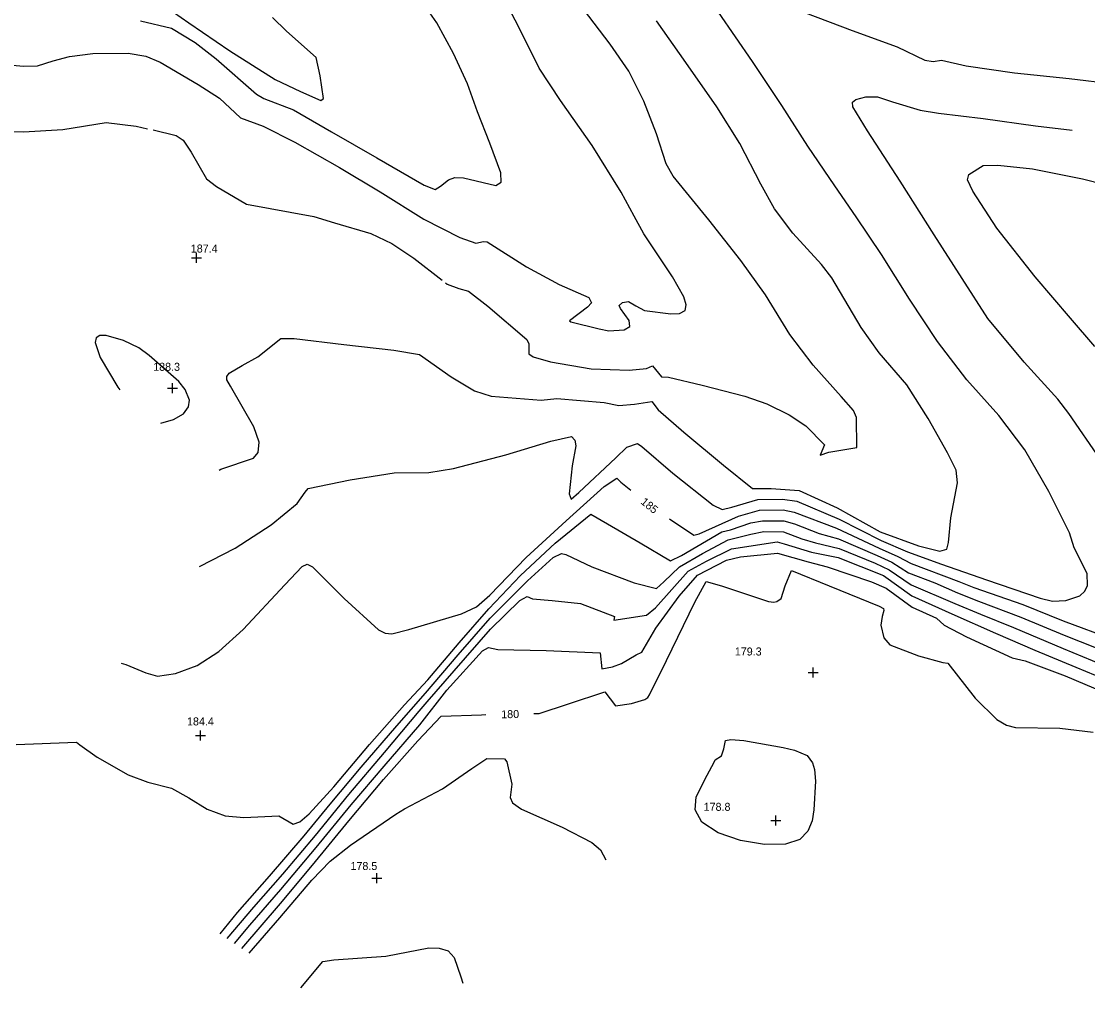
# Model space of a CAD drawing. Extents: x 1467615 to 2003689, y 770235 to 1108726.
# Drawn here: x 1995231.2 to 1995497.6, y 776742.8 to 776984.1 of the extents above; entities that cross this region are included whole.
import ezdxf

# ---------------------------------------------------------------- set-up
doc = ezdxf.new("R2010")
doc.units = 0
for name, color, linetype in [('RD_DTM_Major1', 7, 'Continuous'), ('RD_DTM_Major1_Lbl', 7, 'Continuous'), ('RD_DTM_Minor1', 7, 'Continuous'), ('RD_DTM_Spot_Elev', 7, 'Continuous')]:
    doc.layers.add(name, color=color, linetype=linetype)

msp = doc.modelspace()

# ---------------------------------------------------------------- linework, layer by layer
at = {"layer": 'RD_DTM_Major1'}
for points in [[(1995261.03, 776984.21), (1995268.76, 776982.39), (1995274.67, 776978.74), (1995279.91, 776974.68), (1995289.96, 776965.88), (1995291.8, 776964.78), (1995299.26, 776961.94), (1995308.7, 776956.45), (1995320.06, 776949.96), (1995331.84, 776943.17), (1995334.63, 776942.12), (1995335.96, 776942.91), (1995337.91, 776944.52), (1995339.51, 776945.04), (1995341.68, 776945.01), (1995349.73, 776943.07), (1995351.1, 776943.87), (1995351.03, 776946.28), (1995348.29, 776953.61), (1995345.17, 776961.45), (1995342.71, 776968.47), (1995339.23, 776976.07), (1995334.99, 776983.68), (1995329.2, 776992.08)], [(1995500.84, 776874.64), (1995492.92, 776886.19), (1995490.12, 776889.74), (1995481.78, 776898.96), (1995472.65, 776909.85), (1995466.23, 776919.89), (1995459.29, 776930.79), (1995450.75, 776944.13), (1995442.63, 776956.69), (1995438.94, 776962.71), (1995438.84, 776963.87), (1995439.7, 776964.51), (1995442.23, 776965.25), (1995445.13, 776965.19), (1995448.82, 776963.94), (1995455.8, 776961.9), (1995460.38, 776961.11), (1995471.53, 776959.8), (1995484.54, 776958.01), (1995493.76, 776956.9)], [(1995256.14, 776823.79), (1995257.37, 776823.52), (1995262.34, 776821.39), (1995265.28, 776820.62), (1995269.77, 776821.25), (1995275.17, 776823.28), (1995280.6, 776826.72), (1995286.69, 776832.21), (1995297.04, 776843.38), (1995301.4, 776848), (1995302.67, 776848.54), (1995303.96, 776847.91), (1995311.85, 776840.01), (1995320.45, 776832.16), (1995322.16, 776831.32), (1995323.75, 776831.19), (1995328.03, 776832.26), (1995341.19, 776836.15), (1995344.9, 776837.87), (1995348.28, 776840.77), (1995357.31, 776850.19), (1995367.34, 776859.4), (1995376.79, 776867.94), (1995380.01, 776870.02), (1995381.01, 776869), (1995383.45, 776867.01)], [(1995393.11, 776859.87), (1995399.25, 776855.78), (1995400.57, 776856.08), (1995410.42, 776860.56), (1995415.59, 776862.01), (1995421.53, 776862.08), (1995424.32, 776861.54), (1995434.84, 776857.56), (1995445.54, 776852.57), (1995450.21, 776850.49), (1995453.48, 776848.69), (1995465.42, 776844.19), (1995469.16, 776842.71), (1995481.38, 776838.45), (1995491.5, 776834.36), (1995504.07, 776829.72)], [(1995359.25, 776811.23), (1995360.57, 776811.25), (1995367.96, 776813.66), (1995377.02, 776816.68), (1995379.68, 776813.2), (1995383.64, 776813.76), (1995387, 776814.77), (1995387.7, 776815.26), (1995388.14, 776815.94), (1995392.36, 776824.49), (1995399.45, 776839.06), (1995402.27, 776844.25), (1995406.11, 776843.11), (1995417.85, 776839.22), (1995419.25, 776839.06), (1995419.95, 776839.18), (1995421.03, 776839.97), (1995422.06, 776843.1), (1995423.66, 776846.93), (1995433.01, 776843.13), (1995445.51, 776838.09), (1995446.63, 776837.49), (1995446.73, 776837.01), (1995446.26, 776835.48), (1995445.97, 776833.3), (1995446.7, 776830.18), (1995448.17, 776828.4), (1995455.35, 776825.65), (1995461.42, 776823.98), (1995462.69, 776823.81), (1995469.48, 776815.1), (1995474.93, 776809.75), (1995477.33, 776808.35), (1995479.55, 776807.77), (1995490.64, 776807.61), (1995498.98, 776806.58)], [(1995286.29, 776752.63), (1995296, 776763.85), (1995303.96, 776773.36), (1995313.03, 776784.48), (1995321.73, 776794.77), (1995330.27, 776804.41), (1995336.08, 776810.6), (1995346.18, 776810.96), (1995347.25, 776810.98)]]:
    msp.add_lwpolyline(points, dxfattribs=at)
at = {"layer": 'RD_DTM_Minor1'}
for points in [[(1995218, 776974.14), (1995231.79, 776972.88), (1995235.24, 776972.99), (1995239.16, 776974.21), (1995243.25, 776975.3), (1995249.13, 776976.03), (1995257.95, 776976.13), (1995262.3, 776975.37), (1995265.89, 776973.85), (1995275.45, 776968.3), (1995280.73, 776964.92), (1995286.02, 776959.93), (1995291.64, 776957.92), (1995299.54, 776953.87), (1995310.73, 776947.61), (1995320.91, 776941.53), (1995331.81, 776934.7), (1995340.8, 776930.11), (1995344.78, 776928.68), (1995346.69, 776929.07), (1995347.57, 776929.02), (1995357.42, 776922.75), (1995365.57, 776918.34), (1995372.96, 776915.13), (1995373.67, 776913.79), (1995372.64, 776912.68), (1995368.14, 776909.25), (1995368.54, 776909.05), (1995375.61, 776907.26), (1995378, 776906.8), (1995381.81, 776907.04), (1995383.27, 776907.86), (1995383.1, 776909.39), (1995380.88, 776912.35), (1995380.56, 776913.12), (1995381.43, 776913.87), (1995382.92, 776914.08), (1995384.76, 776913.06), (1995386.87, 776911.89), (1995393.51, 776911.04), (1995395.64, 776911.15), (1995397.04, 776911.84), (1995397.34, 776913.26), (1995396.72, 776915.29), (1995393.87, 776920.31), (1995386.77, 776931.03), (1995384.31, 776935.39), (1995381.09, 776941.44), (1995373.85, 776953.03), (1995365.92, 776964.31), (1995360.58, 776972.4), (1995355.34, 776982.93), (1995349.47, 776994.18)], [(1995337.18, 776918.8), (1995337.62, 776918.45), (1995340.56, 776917.4), (1995342.92, 776916.68), (1995347.75, 776912.95), (1995357.48, 776904.59), (1995357.99, 776903.54), (1995358.04, 776901.08), (1995359.08, 776900.28), (1995363.41, 776899.09), (1995373.61, 776897.34), (1995383.1, 776896.96), (1995387.39, 776897.42), (1995388.91, 776898.09), (1995391.14, 776895.33), (1995392.87, 776895.23), (1995401.33, 776893.22), (1995411.95, 776890.45), (1995417.49, 776888.61), (1995423.03, 776885.84), (1995427.18, 776883.07), (1995431.88, 776878.31), (1995430.79, 776875.76), (1995432.96, 776876.53), (1995439.95, 776877.68), (1995439.82, 776885.15), (1995439.11, 776886.91), (1995436, 776890.43), (1995429.04, 776898.2), (1995423.19, 776905.89), (1995417.11, 776915.82), (1995410.94, 776924.37), (1995402.98, 776934.5), (1995394.04, 776945.4), (1995392.28, 776948.51), (1995389.92, 776955.95), (1995386.76, 776964.15), (1995382.99, 776971.64), (1995378.35, 776978.36), (1995370.36, 776988.85)], [(1995267.35, 776987.72), (1995273.04, 776983.67), (1995283.31, 776976.69), (1995294.64, 776969.57), (1995300.95, 776966.58), (1995306.08, 776964.33), (1995306.68, 776964.79), (1995305.9, 776970.47), (1995304.87, 776975.03), (1995297.44, 776981.58), (1995294.01, 776985.01)], [(1995275.76, 776847.97), (1995284.67, 776852.55), (1995293.63, 776858.38), (1995300.18, 776863.68), (1995302.12, 776866.54), (1995302.9, 776867.47), (1995313.36, 776869.58), (1995324.36, 776871.33), (1995333.05, 776871.41), (1995339.23, 776872.45), (1995352.28, 776875.84), (1995363.53, 776879.29), (1995368.68, 776880.42), (1995369.52, 776879.49), (1995369.76, 776878.08), (1995368.81, 776873.11), (1995368.09, 776866.09), (1995368.59, 776864.77), (1995370.52, 776866.43), (1995379.73, 776875.1), (1995382.46, 776877.77), (1995385.15, 776878.67), (1995386.23, 776877.93), (1995393.97, 776871.25), (1995404.09, 776863.23), (1995406.27, 776862.2), (1995408.71, 776862.78), (1995415.2, 776864.69), (1995421.39, 776864.76), (1995424.94, 776864.25), (1995435.5, 776859.77), (1995446.05, 776854.46), (1995452.61, 776851.63), (1995461.08, 776848.58), (1995472.34, 776844.6), (1995485.72, 776840.03), (1995488.8, 776839.3), (1995492.11, 776839.46), (1995495.63, 776840.67), (1995496.9, 776841.77), (1995497.6, 776843.2), (1995497.49, 776846.22), (1995494.23, 776852.65), (1995493.05, 776856.33), (1995487.93, 776866.67), (1995481.95, 776877.12), (1995475.41, 776885.67), (1995467.4, 776894.56), (1995460.11, 776904.1), (1995453.09, 776914.74), (1995446.1, 776925.84), (1995439.8, 776935.24), (1995434.49, 776942.96), (1995427.72, 776952.93), (1995421.21, 776963.09), (1995413.91, 776974), (1995405.43, 776986.35)], [(1995427.16, 776986.17), (1995438.79, 776981.81), (1995450.02, 776977.73), (1995456.92, 776974.36), (1995459.02, 776974.05), (1995461.06, 776974.35), (1995467.25, 776972.98), (1995479.32, 776971.2), (1995492.96, 776969.77), (1995504.07, 776968.43)], [(1995280.62, 776871.98), (1995281.04, 776872.23), (1995289.21, 776875.04), (1995290.43, 776876.45), (1995290.68, 776878.97), (1995289.32, 776882.84), (1995283.46, 776892.98), (1995282.57, 776894.52), (1995282.56, 776895.37), (1995283.15, 776896.26), (1995286.37, 776898.15), (1995290.3, 776900.3), (1995296.04, 776904.92), (1995299.43, 776904.87), (1995311.8, 776903.41), (1995324.26, 776901.97), (1995330.66, 776900.88), (1995338.6, 776895.32), (1995344.43, 776891.84), (1995348.63, 776890.49), (1995361.06, 776889.48), (1995364.99, 776889.89), (1995376.87, 776888.87), (1995380.52, 776888.13), (1995384.39, 776888.46), (1995388.75, 776889.18), (1995390.34, 776887.11), (1995396.72, 776881.53), (1995406.62, 776873.26), (1995413.85, 776867.44), (1995418.52, 776867.47), (1995425.55, 776866.97), (1995435.05, 776862.58), (1995445.75, 776856.64), (1995455.35, 776853.11), (1995460.67, 776851.81), (1995462.41, 776852.3), (1995462.88, 776853.96), (1995463.4, 776860.13), (1995465.11, 776868.82), (1995464.73, 776871.97), (1995462.62, 776876.36), (1995457.73, 776884.9), (1995452.42, 776893.29), (1995445.52, 776901.29), (1995441.01, 776907.64), (1995433.72, 776920.05), (1995431.08, 776923.33), (1995423.98, 776931.21), (1995419.36, 776937.25), (1995415.99, 776943.41), (1995410.71, 776953.58), (1995405.01, 776962.68), (1995397.21, 776973.78), (1995389.94, 776984.22)], [(1995222.07, 776956.84), (1995231.79, 776956.49), (1995241.61, 776957.02), (1995252.41, 776958.77), (1995259.95, 776957.92), (1995262.78, 776957.26)], [(1995264.15, 776956.94), (1995269.94, 776955.59), (1995271.69, 776954.38), (1995273.7, 776951.38), (1995277.49, 776944.77), (1995279.98, 776942.82), (1995287.5, 776938.4), (1995304.29, 776935.36), (1995309.5, 776933.72), (1995318.55, 776931.08), (1995323.83, 776928.58), (1995329.31, 776924.96), (1995336.33, 776919.46)], [(1995499.41, 776902.88), (1995493.3, 776909.92), (1995484.46, 776920.25), (1995474.95, 776932.41), (1995468.94, 776941.67), (1995467.62, 776944.49), (1995467.92, 776945.84), (1995471.46, 776948.11), (1995475.16, 776948.17), (1995483.86, 776947.2), (1995496.32, 776944.75), (1995507.81, 776941.79)], [(1995266.1, 776883.75), (1995269.22, 776884.62), (1995271.74, 776886.05), (1995273.03, 776887.78), (1995273.23, 776889.49), (1995272.17, 776892.14), (1995270.57, 776894.18), (1995263.14, 776900.65), (1995260.57, 776902.56), (1995256.79, 776904.4), (1995252.44, 776905.65), (1995250.81, 776905.64), (1995249.91, 776905.03), (1995249.7, 776903.86), (1995250.96, 776900.14), (1995255.37, 776892.75), (1995255.83, 776892.09)], [(1995229.95, 776803.56), (1995245.05, 776804.07), (1995245.89, 776803.46), (1995250.15, 776800.35), (1995257.93, 776795.93), (1995262.86, 776794.13), (1995268.73, 776792.66), (1995273.05, 776790.18), (1995277.64, 776787.37), (1995282.18, 776785.68), (1995286.84, 776785.31), (1995295.55, 776785.71), (1995299.13, 776783.63), (1995300.79, 776784.21), (1995303.16, 776786.18), (1995309.27, 776792.93), (1995318.19, 776803.52), (1995326.93, 776813.44), (1995332.76, 776819.64), (1995340.62, 776828.92), (1995347.99, 776837.43), (1995355.91, 776845.73), (1995364.58, 776853.81), (1995373.5, 776861.05), (1995377.66, 776858.61), (1995385.83, 776853.88), (1995393.43, 776849.41), (1995396.18, 776850.68), (1995406.22, 776856.64), (1995408.42, 776857.11), (1995413.47, 776858.85), (1995416.39, 776859.37), (1995421.75, 776859.37), (1995424.35, 776858.58), (1995430.56, 776856.23), (1995435.34, 776854.88), (1995445.04, 776850.68), (1995448.72, 776849.05), (1995452.86, 776846.37), (1995459.39, 776843.87), (1995465.13, 776841.37), (1995470.37, 776839.3), (1995480.9, 776835.31), (1995491.74, 776830.78), (1995503.76, 776826.11)], [(1995280.9, 776756.25), (1995285.26, 776761.56), (1995293.22, 776770.66), (1995301.86, 776780.68), (1995308.4, 776788.62), (1995316.12, 776797.87), (1995325, 776808.19), (1995332.22, 776816.36), (1995340.37, 776825.87), (1995348.39, 776835.04), (1995357.65, 776844.4), (1995364.12, 776850.21), (1995366.18, 776851.23), (1995367.26, 776850.92), (1995373.77, 776847.89), (1995384.29, 776843.86), (1995389.92, 776842.49), (1995391.71, 776844.13), (1995395.65, 776847.9), (1995401.39, 776851.19), (1995407.83, 776854.63), (1995413.46, 776856.03), (1995416.7, 776856.69), (1995421.62, 776856.6), (1995426.19, 776854.84), (1995429.59, 776853.89), (1995435.5, 776852.42), (1995444.53, 776848.79), (1995448.02, 776847.13), (1995453.55, 776843.38), (1995464.42, 776838.75), (1995470.87, 776836.1), (1995479.05, 776832.74), (1995491.52, 776827.48), (1995503.57, 776822.53)], [(1995282.69, 776755.05), (1995289.33, 776762.94), (1995296.58, 776771.17), (1995304.68, 776780.84), (1995313.05, 776791.01), (1995321.99, 776801.51), (1995330.61, 776811.87), (1995332.62, 776814.19), (1995339.35, 776821.94), (1995348.46, 776832.33), (1995355.77, 776839.47), (1995357.58, 776840.44), (1995358.93, 776839.91), (1995363.81, 776839.5), (1995370.92, 776838.7), (1995379.42, 776835.45), (1995379.28, 776834.6), (1995387.39, 776835.78), (1995389.63, 776837.61), (1995397.79, 776846.78), (1995402.43, 776849.3), (1995408.67, 776852.37), (1995420.06, 776854.08), (1995421.81, 776853.64), (1995428.62, 776851.54), (1995435.31, 776850.21), (1995446.63, 776845.74), (1995453.65, 776840.61), (1995463.71, 776836.13), (1995474.61, 776831.32), (1995484.43, 776827.04), (1995494.68, 776822.86), (1995504.31, 776818.8)], [(1995284.49, 776753.84), (1995288.32, 776758.38), (1995296.09, 776767.29), (1995304.88, 776777.79), (1995313.62, 776788.47), (1995321.86, 776798.14), (1995330.81, 776808.47), (1995337.53, 776817.11), (1995346.46, 776826.94), (1995347.96, 776827.76), (1995350.29, 776827.25), (1995362.36, 776826.96), (1995375.79, 776826.38), (1995376.23, 776822.4), (1995378.89, 776822.91), (1995381.17, 776823.77), (1995384.86, 776825.9), (1995386.22, 776826.56), (1995389.76, 776832.54), (1995395.54, 776840.56), (1995400.14, 776845.79), (1995407.41, 776849.57), (1995410.89, 776850.34), (1995420.12, 776851.29), (1995427.79, 776849.1), (1995432.55, 776847.85), (1995443.57, 776844.16), (1995447.25, 776842.58), (1995453.79, 776837.81), (1995459.84, 776835.07), (1995461.73, 776833.34), (1995467.37, 776830.42), (1995478.71, 776825.13), (1995481.99, 776824.41), (1995492.01, 776820.64), (1995501.83, 776816.51)], [(1995424.41, 776802.09), (1995427.55, 776800.75), (1995428.87, 776798.91), (1995429.4, 776797.29), (1995429.63, 776794.33), (1995429.19, 776787.21), (1995428.75, 776784.44), (1995427.73, 776781.85), (1995425.68, 776779.78), (1995422.14, 776778.6), (1995416.92, 776778.57), (1995410.91, 776779.59), (1995405.3, 776781.5), (1995401.24, 776784.1), (1995399.58, 776787.19), (1995399.81, 776790.43), (1995402.57, 776795.85), (1995404.3, 776799.09), (1995404.55, 776799.7), (1995406.12, 776800.72), (1995406.76, 776802.48), (1995407.17, 776804.51), (1995408.43, 776804.76), (1995411.68, 776804.51), (1995421.51, 776802.81), (1995424.41, 776802.09)], [(1995288.14, 776751.39), (1995295.78, 776760.23), (1995303.8, 776769.69), (1995308.37, 776774.36), (1995313.46, 776778.41), (1995324.83, 776786.16), (1995326.98, 776787.48), (1995336.44, 776792.48), (1995343.8, 776797.55), (1995347.54, 776799.99), (1995351.93, 776799.96), (1995352.55, 776799.22), (1995353.74, 776793.58), (1995353.34, 776790.26), (1995353.94, 776788.95), (1995356.2, 776787.34), (1995366.31, 776782.9), (1995373.74, 776779.05), (1995375.91, 776777.19), (1995377.26, 776774.69)], [(1995301.07, 776742.81), (1995306.57, 776749.35), (1995309.34, 776749.76), (1995322.28, 776750.69), (1995333, 776752.72), (1995335.65, 776752.71), (1995337.84, 776751.98), (1995339.33, 776750.33), (1995341.03, 776745.52), (1995341.56, 776743.95)]]:
    msp.add_lwpolyline(points, dxfattribs=at)
at = {"layer": 'RD_DTM_Spot_Elev'}
for p, q in [((1995273.75, 776925), (1995276.25, 776925)), ((1995275, 776923.75), (1995275, 776926.25)), ((1995267.73, 776892.46), (1995270.23, 776892.46)), ((1995268.98, 776891.21), (1995268.98, 776893.71)), ((1995427.79, 776821.47), (1995430.29, 776821.47)), ((1995429.04, 776820.22), (1995429.04, 776822.72)), ((1995274.75, 776805.75), (1995277.25, 776805.75)), ((1995276, 776804.5), (1995276, 776807)), ((1995418.44, 776784.51), (1995420.94, 776784.51)), ((1995419.69, 776783.26), (1995419.69, 776785.76)), ((1995318.8, 776770.12), (1995321.3, 776770.12)), ((1995320.05, 776768.87), (1995320.05, 776771.37))]:
    msp.add_line(p, q, dxfattribs=at)

# ---------------------------------------------------------------- texts
at = {"layer": 'RD_DTM_Major1_Lbl'}
for s, rotation, p in [('185', 320.8794, (1995385.8, 776863.81)), ('180', 1.1654, (1995351.14, 776810.06))]:
    msp.add_text(s, height=2, rotation=rotation, dxfattribs=at).set_placement(p)
at = {"layer": 'RD_DTM_Spot_Elev'}
for s, p in [('187.4', (1995273.57, 776926.34)), ('188.3', (1995264.18, 776896.81)), ('179.3', (1995409.47, 776825.74)), ('184.4', (1995272.63, 776808.28)), ('178.8', (1995401.68, 776786.96)), ('178.5', (1995313.46, 776772.19))]:
    msp.add_text(s, height=2, dxfattribs=at).set_placement(p)

doc.saveas('drawing.dxf')
